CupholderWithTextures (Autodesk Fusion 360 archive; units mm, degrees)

design "Final Project" references "Servo_motor", "EIP Cupholder PCB", "Arcade Button_30mm"
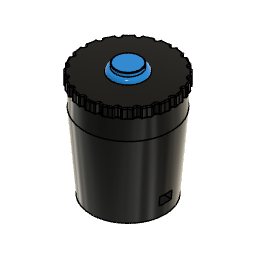
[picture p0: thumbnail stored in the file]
parameter "CupHolderBottomDiameter" = 76.2
parameter "CupHolderTopDiameter" = 88.9
parameter "CupHolderHeight" = 76.2
parameter "CupHolderThickness" = 10 comment "Only for visual CAD  purposes"
parameter "CupHolderTolerance" = 2 comment "Between cup holder and the mechanism case"
parameter "LidHeight" = 30
parameter "CupHolderCaseThickness" = 10
parameter "LockingMechanismProtrusionWidth" = 5
parameter "LockingMechanismTolerance" = 1
parameter "LockingMechanismProtrusionHeight" = 5
parameter "LockingMechanismProtrusionDistance" = 5
parameter "LockingMechanismAngle" = 20
parameter "ArcadeButtonDiameter" = 30
parameter "MirrorAttachmentCurlThickness" = 2
sketch "Sketch2" plane through (0, 0, 0) normal (0, 0, 1) x axis (1, 0, 0)
  circle C1 centre (0, 0) radius 38.1
  point P1 (0, 0)
  point P2 (0, 0)
  coincident P1 P2
  dimension "d3" diameter C1 = 76.2 (= "CupHolderBottomDiameter")
work_plane "WorkPlane1" sketch "Sketch2" AlongDistance 76.2 (= "CupHolderHeight")
sketch "Sketch3" plane through (0, 0, 76.2) normal (0, 0, 1) x axis (1, 0, 0)
  circle C1 centre (0, 0) radius 44.45
  point P1 (0, 0)
  point P2 (0, 0)
  coincident P1 P2
  dimension "d6" diameter C1 = 88.9 (= "CupHolderTopDiameter")
loft "Loft1" sketch "Sketch2" + "Sketch3"
sketch "Sketch4" plane through (0, 0, 0) normal (0, 0, 1) x axis (1, 0, 0)
  circle C1 centre (0, 0) radius 88.9
  point P1 (0, 0)
  point P2 (0, 0)
  coincident P1 P2
  dimension "d7" diameter C1 = 177.8 (= "CupHolderTopDiameter * 2")
extrude "Extrude1" new body sketch "Sketch4" along normal blind 76.2 (= "CupHolderHeight")
extrude "Extrude2" new body of existing geometry blind 10 (= "CupHolderThickness") bodies "CupHolder"
combine "Combine2"
combine "Combine1"
sketch "Sketch1" plane through (0, 0, 0) normal (0, 0, 1) x axis (1, 0, 0)
  circle C1 centre (0, 0) radius 44.45
  point P1 (0, 0)
  point P2 (0, 0)
  coincident P1 P2
  dimension "d15" diameter C1 = 88.9 (= "CupHolderTopDiameter")
extrude "Extrude1" new body sketch "Sketch1" along normal blind 76.2 (= "CupHolderHeight")
combine "Combine1"
copy_paste "CutPaste1"
offset_faces "OffsetFaces1"
extrude "Extrude2" add of existing geometry blind 30 (= "LidHeight")
shell "Shell2" innerThickness 10 (= "CupHolderThickness")
split "Split4" bodies "CupHolderCase"
sketch "Sketch4" plane through (0, 0, 96.2) normal (0, 0, -1) x axis (1, 0, 0)
  circle C1 centre (0, 0) radius 42.4431
  circle C2 centre (0, 0) radius 32.4431
extrude "Extrude4" new body sketch "Sketch4" profile of C2 along normal blind 20 (= "LidHeight - CupHolderThickness")
combine "Combine4"
sketch "Sketch5" plane through (0, 0, 76.2) normal (0, 0, -1) x axis (1, 0, 0)
  line L1 (0, -32.4431) -> (0, -36.9654)
  line L2 (3, -32.4431) -> (0, -32.4431)
  line L3 (3, -25.4431) -> (3, -32.4431)
  line L4 (0, -25.4431) -> (3, -25.4431)
  line L5 (-3, -32.4431) -> (0, -32.4431)
  line L6 (-3, -25.4431) -> (-3, -32.4431)
  line L7 (0, -25.4431) -> (-3, -25.4431)
  circle C1 centre (0, 0) radius 32.4431
  point P4 (0, -32.4431)
  point P8 (0, -32.4431)
  point P5 (3, -32.4431)
  point P9 (-3, -32.4431)
  point P6 (3, -25.4431)
  point P10 (-3, -25.4431)
  point P7 (0, -25.4431)
  point P11 (0, -25.4431)
  coincident C1 P4
  vertical L1
  tangent C1 L2
  perpendicular L1 L2
  perpendicular L2 L3
  perpendicular L3 L4
  symmetric P4 L1 P8
  symmetric L1 P5 P9
  symmetric L1 P6 P10
  symmetric L1 P7 P11
  dimension "d37" distance P4 P5 = 3 (= "LockingMechanismProtrusionWidth / 2 + LockingMechanismTolerance / 2")
  dimension "d39" distance P5 P6 = 7 (= "LockingMechanismProtrusionDistance + CupHolderTolerance")
extrude "Extrude5" cut sketch "Sketch5" profile of C1 L3 L4 L6 L7 against normal blind 20
sketch "Sketch6" plane through (0, 0, 96.2) normal (0, 0, -1) x axis (1, 0, 0)
  line L1 (3, -25.4431) -> (3, -32.3041)
  line L2 (-3, -25.4431) -> (3, -25.4431)
  line L3 (-3, -32.3041) -> (-3, -25.4431)
  line L4 (-8.702, -23.9087) -> (0, 0)
  line L5 (0, -25.4431) -> (0, 0)
  line L6 (-11.0962, -30.4865) -> (-8.702, -23.9087)
  line L7 (-3, -25.2656) -> (-3, -25.4431)
  arc A1 centre (0, 0) radius 32.4431 clockwise from (-3, -32.3041) to (3, -32.3041)
  circle C1 centre (0, 0) radius 42.4431
  arc A2 centre (0, 0) radius 25.4431 clockwise from (0, -25.4431) to (-8.702, -23.9087)
  point P9 (0, -25.4431)
  point P1 (0, 0)
  point P7 (0, 0)
  point P10 (-11.0962, -30.4865)
  point P6 (-3, -25.4431)
  point P11 (-3, -25.4431)
  point P12 (-3, -25.2656)
  midpoint L2 P9
  coincident P1 P7
  coincident A1 P10
  parallel L4 L6
  coincident P6 P11
  coincident A2 P12
  perpendicular L2 L7
  dimension "d43" angle L4 L5 = 20 (= "LockingMechanismAngle")
extrude "Extrude6" cut sketch "Sketch6" profile of A1 L3 A2 L6 L7 along normal blind 6 (= "LockingMechanismProtrusionHeight + LockingMechanismTolerance")
extrude "Extrude7" cut sketch "Sketch6" profile of L2 A2 L7 along normal blind 20
sketch "Sketch7" plane through (0, 0, 0) normal (0.9397, 0.342, 0) x axis (-0.342, 0.9397, 0)
  line L1 (25.4431, 96.2) -> (32.4431, 96.2)
  line L2 (25.4431, 90.2) -> (25.4431, 96.2)
  line L3 (32.4431, 90.2) -> (25.4431, 90.2)
  line L4 (32.4431, 96.2) -> (32.4431, 90.2)
  line L5 (32.4431, 91.2) -> (32.4431, 90.2)
  line L6 (25.4431, 91.2) -> (32.4431, 91.2)
  point P5 (32.4431, 90.2)
  point P6 (32.4431, 90.2)
  point P7 (32.4431, 91.2)
  point P8 (25.4431, 91.2)
  coincident P5 P6
  coincident L4 P7
  coincident L2 P8
  perpendicular L2 L6
  dimension "d48" distance P6 P7 = 1 (= "LockingMechanismTolerance")
loft "Loft3" sketch "Sketch7"
circular_pattern "C-Pattern1" TotalAngle 360
fillet "Fillet2" radius 1 1
sketch "Sketch8" plane through (0, 0, 96.2) normal (0, 0, 1) x axis (-1, 0, 0)
  line L1 (2.2086, -32.4642) -> (-0.2913, -32.4418)
  line L2 (2.2535, -27.4644) -> (2.2086, -32.4642)
  line L3 (-0.4431, -27.4402) -> (2.2535, -27.4644)
  line L4 (-0.4431, -27.4402) -> (-0.2913, -32.4418)
  line L5 (-2.7852, -32.6157) -> (-0.2913, -32.4418)
  line L6 (-3.1332, -27.6279) -> (-2.7852, -32.6157)
  line L7 (-0.4431, -27.4402) -> (-3.1332, -27.6279)
  circle C1 centre (0, 0) radius 32.4431
  circle C2 centre (0, 0) radius 42.4431
  point P3 (-0.2913, -32.4418)
  point P7 (-0.2913, -32.4418)
  point P4 (2.2086, -32.4642)
  point P8 (-2.7852, -32.6157)
  point P5 (2.2535, -27.4644)
  point P9 (-3.1332, -27.6279)
  point P6 (-0.4431, -27.4402)
  point P10 (-0.4431, -27.4402)
  coincident C1 P3
  tangent C1 L1
  perpendicular L1 L2
  perpendicular L2 L3
  symmetric P3 L4 P7
  symmetric P4 L4 P8
  symmetric P5 L4 P9
  symmetric P6 L4 P10
  dimension "d51" distance P3 P4 = 2.5 (= "LockingMechanismProtrusionWidth / 2")
  dimension "d52" distance P4 P5 = 5
extrude "Extrude8" add sketch "Sketch8" profile of C1 L2 L3 L6 L7 no distance stored
fillet "Fillet1" radius 1
circular_pattern "C-Pattern2" TotalAngle 360
sketch "Sketch9" plane through (0, 0, 106.2) normal (0, 0, 1) x axis (-1, 0, 0)
  line L1 (-13.5367, -40.2265) -> (0, 0)
  line L2 (-0.4435, -42.4408) -> (0, 0)
  line L3 (0, 0) -> (-7.0772, -41.8489)
  line L4 (-19.6113, -115.9654) -> (-7.0772, -41.8489)
  curve K1 (-7.4119, -43.8277) -> (-0.4435, -42.4408)
  curve K2 (-0.847, -42.4391) -> (-0.04, -42.4424)
  line L5 (-10.6726, -43.2763) -> (-7.4119, -43.8277)
  curve K3 (-9.0422, -43.552) -> (-5.7815, -44.1034)
  curve K4 (-7.4119, -43.8277) -> (-13.5367, -40.2265)
  curve K5 (-13.1551, -40.3576) -> (-13.9183, -40.0954)
  curve K6 (-5.7815, -44.1034) -> (-9.0422, -43.552)
  circle C1 centre (0, 0) radius 42.4431
  arc A1 centre (0, 0) radius 42.4431 clockwise from (-0.4435, -42.4408) to (-13.5367, -40.2265)
  point P5 (-0.4435, -42.4408)
  point P1 (0, 0)
  point P3 (0, 0)
  point P6 (-7.0772, -41.8489)
  point P7 (-7.0772, -41.8489)
  point P8 (0, 0)
  point P9 (-7.0772, -41.8489)
  point P12 (-7.4119, -43.8277)
  point P17 (-9.0422, -43.552)
  point P18 (-13.5367, -40.2265)
  point P11 (-4.9088, -86.9573)
  point P19 (-23.9577, -83.7359)
  point P20 (-7.4119, -43.8277)
  point P13 (-0.04, -42.4424)
  point P21 (-13.9183, -40.0954)
  point P14 (-0.847, -42.4391)
  point P22 (-13.1551, -40.3576)
  point P16 (-5.7815, -44.1034)
  point P23 (-9.0422, -43.552)
  point P24 (-5.7815, -44.1034)
  coincident C1 P5
  coincident P1 P3
  midpoint A1 P6
  coincident P6 P7
  coincident P1 P8
  coincident P6 P9
  parallel L3 L4
  coincident L4 P12
  midpoint P5 K2
  perpendicular L4 L5
  midpoint P12 K3
  midpoint L5 P17
  parallel L5 K3
  symmetric P5 L4 P18
  symmetric L4 P11 P19
  symmetric L4 P12 P20
  symmetric L4 P13 P21
  symmetric L4 P14 P22
  symmetric L4 P16 P23
  symmetric L4 P17 P24
  dimension "d64" angle L1 L2 = 18 (= "( 360 / NumGripsTopLid ) * 1 deg")
  dimension "d153" distance P8 P12 = 44.45 (= "CupHolderTopDiameter / 2")
extrude "Extrude9" new body sketch "Sketch9" profile of C1 K1 K4 against normal blind 10
combine "Combine6"
circular_pattern "C-Pattern4" TotalAngle 360
component_from_bodies "Body->Comp1"
component_from_bodies "Body->Comp2"
fillet "Fillet1" radius 1
fillet "Fillet2" radius 1
sketch "Sketch10" plane through (0, 0, 76.2) normal (0, 0, -1) x axis (1, 0, 0)
  line L1 (24.1136, -4) -> (31.1876, -4)
  line L2 (24.4431, 4) -> (24.4431, 0)
  line L3 (31.1876, 4) -> (24.4431, 4)
  line L4 (4, 24.1136) -> (4, 31.1876)
  line L5 (-4, 24.4431) -> (0, 24.4431)
  line L6 (-4, 31.1876) -> (-4, 24.4431)
  line L7 (-24.1136, 4) -> (-31.1876, 4)
  line L8 (-24.4431, -4) -> (-24.4431, 0)
  line L9 (-31.1876, -4) -> (-24.4431, -4)
  line L10 (-4, -24.1136) -> (-4, -31.1876)
  line L11 (4, -24.4431) -> (0, -24.4431)
  line L12 (4, -31.1876) -> (4, -24.4431)
  arc A1 centre (0, 0) radius 24.4431 clockwise from (24.4431, 0) to (24.1136, -4)
  arc A2 centre (0, 0) radius 31.4431 clockwise from (4, 31.1876) to (31.1876, 4)
  arc A3 centre (0, 0) radius 24.4431 clockwise from (0, 24.4431) to (4, 24.1136)
  arc A4 centre (0, 0) radius 31.4431 clockwise from (-31.1876, 4) to (-4, 31.1876)
  arc A5 centre (0, 0) radius 24.4431 clockwise from (-24.4431, 0) to (-24.1136, 4)
  arc A6 centre (0, 0) radius 31.4431 clockwise from (-4, -31.1876) to (-31.1876, -4)
  arc A7 centre (0, 0) radius 24.4431 clockwise from (0, -24.4431) to (-4, -24.1136)
  arc A8 centre (0, 0) radius 31.4431 clockwise from (31.1876, -4) to (4, -31.1876)
  circle C1 centre (0, 0) radius 22.5
  concentric A1 C1
  dimension "d155" diameter C1 = 45 (= "ArcadeButtonDiameter + 15 mm")
extrude "Extrude1" cut sketch "Sketch10" profile of C1 against normal blind 20
fillet "Fillet3" radius 1
fillet "Fillet4" radius 1
sketch "Sketch11" plane through (0, 0, 96.2) normal (0, 0, -1) x axis (1, 0, 0)
  circle C1 centre (0, 0) radius 21.5
  circle C2 centre (0, 0) radius 15
  point P1 (0, 0)
  point P3 (0, 0)
  coincident P1 P3
  dimension "d82" diameter C2 = 30 (= "ArcadeButtonDiameter")
extrude "Extrude2" cut sketch "Sketch11" profile of C2 against normal blind 10
component_insert "Component Insert1"
joint "Assemble1" alignAngle 0 alignOffsetX 0 alignOffsetY 0 alignOffsetZ 0
as_built_joint "As-built1" OffsetX 0 OffsetY 0 OffsetZ 0 AngleZ 0 AngleMaximum 0
joint "Assemble1" alignAngle 0 alignOffsetX 0 alignOffsetY 0 alignOffsetZ -130 DistanceMaximum 0 DistanceRest 0
base_feature "Base Feature1"
base_feature "Base Feature1"
base_feature "Base Feature1"
base_feature "Base Feature1"
base_feature "Base Feature1"
base_feature "Base Feature1"
base_feature "Base Feature1"
base_feature "Base Feature1"
base_feature "Base Feature1"
base_feature "Base Feature1"
base_feature "Base Feature1"
sketch "Sketch4" plane through (-0.0164, 0, -21.4157) normal (-0.0008, 0, -1) x axis (0, -1, 0)
  line L1 (-46.2621, -82.9366) -> (-46.2621, -20.9366)
  line L2 (51.0689, -82.9366) -> (-46.2621, -82.9366)
  line L3 (51.0689, -20.9366) -> (51.0689, -82.9366)
  line L4 (-46.2621, -20.9366) -> (51.0689, -20.9366)
  line L5 (8.573, -42.2771) -> (8.573, -31.2771)
  line L6 (-4.427, -44.2771) -> (6.573, -44.2771)
  line L7 (-6.427, -31.2771) -> (-6.427, -42.2771)
  line L8 (6.573, -29.2771) -> (-4.427, -29.2771)
  line L9 (-123.9966, -211.3616) -> (128.8034, -211.3616)
  line L10 (-123.9966, -20.9366) -> (-123.9966, -211.3616)
  line L11 (128.8034, -20.9366) -> (-123.9966, -20.9366)
  line L12 (128.8034, -211.3616) -> (128.8034, -20.9366)
  arc A1 centre (6.573, -42.2771) radius 2 clockwise from (8.573, -42.2771) to (6.573, -44.2771)
  arc A2 centre (-4.427, -42.2771) radius 2 clockwise from (-4.427, -44.2771) to (-6.427, -42.2771)
  arc A3 centre (-4.427, -31.2771) radius 2 clockwise from (-6.427, -31.2771) to (-4.427, -29.2771)
  arc A4 centre (6.573, -31.2771) radius 2 clockwise from (6.573, -29.2771) to (8.573, -31.2771)
  point P22 (2.4034, -20.9366)
  point P23 (2.4034, -20.9366)
  point P18 (128.8034, -211.3616)
  point P19 (-123.9966, -211.3616)
  point P20 (-123.9966, -20.9366)
  horizontal L9
  vertical L10
  horizontal L11
  vertical L12
  midpoint L11 P22
  midpoint L4 P23
  coincident P22 P23
  dimension "d128" distance P18 P19 = 252.8
  dimension "d129" distance P19 P20 = 190.425
extrude "Extrude2" new body sketch "Sketch4" profile of L1 L2 L3 L9 L10 L11 L12 against normal blind 2
combine "Combine3"
copy_paste_bodies "CutPasteBodies1"
remove_body "RemoveBody1"
sketch "Sketch5" plane through (-0.0164, 0, -21.4157) normal (-0.0008, 0, -1) x axis (0, -1, 0)
  line L1 (8.573, -42.2771) -> (8.573, -31.2771)
  line L2 (-4.427, -44.2771) -> (6.573, -44.2771)
  line L3 (-6.427, -31.2771) -> (-6.427, -42.2771)
  line L4 (6.573, -29.2771) -> (-4.427, -29.2771)
  line L5 (-123.9966, -20.9366) -> (128.8034, -20.9366)
  line L6 (-123.9966, -211.3616) -> (-123.9966, -20.9366)
  line L7 (128.8034, -211.3616) -> (-123.9966, -211.3616)
  line L8 (128.8034, -20.9366) -> (128.8034, -211.3616)
  line L9 (121.8034, -211.3616) -> (128.8034, -211.3616)
  line L10 (121.8034, -204.3616) -> (121.8034, -211.3616)
  line L11 (128.8034, -204.3616) -> (121.8034, -204.3616)
  line L12 (128.8034, -211.3616) -> (128.8034, -204.3616)
  arc A1 centre (6.573, -42.2771) radius 2 clockwise from (8.573, -42.2771) to (6.573, -44.2771)
  arc A2 centre (-4.427, -42.2771) radius 2 clockwise from (-4.427, -44.2771) to (-6.427, -42.2771)
  arc A3 centre (-4.427, -31.2771) radius 2 clockwise from (-6.427, -31.2771) to (-4.427, -29.2771)
  arc A4 centre (6.573, -31.2771) radius 2 clockwise from (6.573, -29.2771) to (8.573, -31.2771)
  circle C1 centre (121.8034, -204.3616) radius 2
  point P17 (128.8034, -211.3616)
  point P18 (128.8034, -211.3616)
  point P20 (121.8034, -204.3616)
  point P22 (121.8034, -204.3616)
  point P21 (128.8034, -204.3616)
  point P19 (121.8034, -211.3616)
  horizontal L9
  vertical L10
  horizontal L11
  vertical L12
  coincident P17 P18
  coincident P20 P22
  dimension "d132" distance P18 P21 = 7
  dimension "d133" distance P18 P19 = 7
  dimension "d134" diameter C1 = 4
extrude "Extrude1" cut sketch "Sketch5" profile of C1 against normal blind 2
work_plane "WorkPlane3"
work_plane "WorkPlane4"
mirror "Mirror1" mirrorStitchTolerance 0.1
mirror "Mirror2" mirrorStitchTolerance 0.1
extrude "Extrude2" cut of existing geometry blind -0.85 (= "-( 2 mm - 1.15 mm )")
sketch "Sketch6" plane through (-0.0157, 0, -20.5657) normal (-0.0008, 0, -1) x axis (0, -1, 0)
  line L1 (8.573, -42.2771) -> (8.573, -31.2771)
  line L2 (-4.427, -44.2771) -> (6.573, -44.2771)
  line L3 (-6.427, -31.2771) -> (-6.427, -42.2771)
  line L4 (6.573, -29.2771) -> (-4.427, -29.2771)
  line L5 (-123.9966, -20.9366) -> (128.8034, -20.9366)
  line L6 (-123.9966, -211.3616) -> (-123.9966, -20.9366)
  line L7 (128.8034, -211.3616) -> (-123.9966, -211.3616)
  line L8 (128.8034, -20.9366) -> (128.8034, -211.3616)
  line L9 (-123.9966, -211.3616) -> (128.8034, -211.3616)
  line L10 (-123.9966, -20.9366) -> (-123.9966, -211.3616)
  line L11 (128.8034, -20.9366) -> (-123.9966, -20.9366)
  line L12 (128.8034, -211.3616) -> (128.8034, -20.9366)
  line L13 (-98.9966, -185.8616) -> (103.8034, -185.8616)
  line L14 (-98.9966, -46.4366) -> (-98.9966, -185.8616)
  line L15 (103.8034, -46.4366) -> (-98.9966, -46.4366)
  line L16 (103.8034, -185.8616) -> (103.8034, -46.4366)
  line L17 (-98.9966, -46.4366) -> (103.8034, -185.8616)
  line L18 (103.8034, -46.4366) -> (-98.9966, -185.8616)
  line L19 (-123.9966, -20.9366) -> (128.8034, -211.3616)
  line L20 (128.8034, -20.9366) -> (-123.9966, -211.3616)
  circle C1 centre (-116.9966, -27.9366) radius 2
  circle C2 centre (-116.9966, -204.3616) radius 2
  circle C3 centre (121.8034, -27.9366) radius 2
  circle C4 centre (121.8034, -204.3616) radius 2
  arc A1 centre (6.573, -42.2771) radius 2 clockwise from (8.573, -42.2771) to (6.573, -44.2771)
  arc A2 centre (-4.427, -42.2771) radius 2 clockwise from (-4.427, -44.2771) to (-6.427, -42.2771)
  arc A3 centre (-4.427, -31.2771) radius 2 clockwise from (-6.427, -31.2771) to (-4.427, -29.2771)
  arc A4 centre (6.573, -31.2771) radius 2 clockwise from (6.573, -29.2771) to (8.573, -31.2771)
  point P19 (-123.9966, -20.9366)
  point P24 (-123.9966, -20.9366)
  point P21 (128.8034, -211.3616)
  point P22 (128.8034, -211.3616)
  point P30 (2.4034, -116.1491)
  point P31 (2.4034, -116.1491)
  point P26 (103.8034, -185.8616)
  point P27 (-98.9966, -185.8616)
  point P29 (103.8034, -46.4366)
  horizontal L9
  vertical L10
  horizontal L11
  vertical L12
  coincident P19 P24
  coincident P21 P22
  horizontal L13
  vertical L14
  horizontal L15
  vertical L16
  midpoint L18 P30
  midpoint L20 P31
  coincident P30 P31
  dimension "d143" distance P26 P27 = 202.8
  dimension "d144" distance P26 P29 = 139.425
extrude "Extrude3" new body sketch "Sketch6" profile of C1 C2 C3 C4 L1 A1 L2 A2 L3 A3 L4 A4 L5 L6 L7 L8 L9 L10 L11 L12 L13 L14 L15 L16 along normal blind 1.125
extrude "Extrude4" new body sketch "Sketch6" profile of L13 L14 L15 L16 along normal blind 1.125
move "Move1"
sketch "Sketch7" plane through (-0.0157, 0, -20.5657) normal (-0.0008, 0, -1) x axis (0, -1, 0)
  line L1 (8.573, -42.2771) -> (8.573, -31.2771)
  line L2 (-4.427, -44.2771) -> (6.573, -44.2771)
  line L3 (-6.427, -31.2771) -> (-6.427, -42.2771)
  line L4 (6.573, -29.2771) -> (-4.427, -29.2771)
  line L5 (-123.9966, -20.9366) -> (128.8034, -20.9366)
  line L6 (-123.9966, -211.3616) -> (-123.9966, -20.9366)
  line L7 (128.8034, -211.3616) -> (-123.9966, -211.3616)
  line L8 (128.8034, -20.9366) -> (128.8034, -211.3616)
  line L9 (-123.9966, -211.3616) -> (128.8034, -211.3616)
  line L10 (-123.9966, -20.9366) -> (-123.9966, -211.3616)
  line L11 (128.8034, -20.9366) -> (-123.9966, -20.9366)
  line L12 (128.8034, -211.3616) -> (128.8034, -20.9366)
  line L13 (-107.0466, -194.4116) -> (111.8534, -194.4116)
  line L14 (-107.0466, -37.8866) -> (-107.0466, -194.4116)
  line L15 (111.8534, -37.8866) -> (-107.0466, -37.8866)
  line L16 (111.8534, -194.4116) -> (111.8534, -37.8866)
  line L17 (-107.0466, -37.8866) -> (111.8534, -194.4116)
  line L18 (111.8534, -37.8866) -> (-107.0466, -194.4116)
  line L19 (-123.9966, -20.9366) -> (128.8034, -211.3616)
  line L20 (128.8034, -20.9366) -> (-123.9966, -211.3616)
  circle C1 centre (-116.9966, -27.9366) radius 2
  circle C2 centre (-116.9966, -204.3616) radius 2
  circle C3 centre (121.8034, -27.9366) radius 2
  circle C4 centre (121.8034, -204.3616) radius 2
  arc A1 centre (6.573, -42.2771) radius 2 clockwise from (8.573, -42.2771) to (6.573, -44.2771)
  arc A2 centre (-4.427, -42.2771) radius 2 clockwise from (-4.427, -44.2771) to (-6.427, -42.2771)
  arc A3 centre (-4.427, -31.2771) radius 2 clockwise from (-6.427, -31.2771) to (-4.427, -29.2771)
  arc A4 centre (6.573, -31.2771) radius 2 clockwise from (6.573, -29.2771) to (8.573, -31.2771)
  point P19 (-123.9966, -20.9366)
  point P24 (-123.9966, -20.9366)
  point P21 (128.8034, -211.3616)
  point P22 (128.8034, -211.3616)
  point P30 (2.4034, -116.1491)
  point P31 (2.4034, -116.1491)
  point P26 (111.8534, -194.4116)
  point P27 (-107.0466, -194.4116)
  point P29 (111.8534, -37.8866)
  horizontal L9
  vertical L10
  horizontal L11
  vertical L12
  coincident P19 P24
  coincident P21 P22
  horizontal L13
  vertical L14
  horizontal L15
  vertical L16
  midpoint L18 P30
  midpoint L20 P31
  coincident P30 P31
  dimension "d149" distance P26 P27 = 218.9
  dimension "d150" distance P26 P29 = 156.525
extrude "Extrude3" new body sketch "Sketch7" profile of C1 C2 C3 C4 L1 L3 A3 L4 A4 L5 L6 L7 L8 L9 L10 L11 L12 L13 L14 L15 L16 along normal blind 1.15
copy_paste_bodies "CutPasteBodies2"
sketch "pcb-sketch" plane through (0, 0, 183.1) normal (0, 0, -1) x axis (1, 0, 0)
  circle C1 centre (0, 0) radius 15
  circle C2 centre (0, 0) radius 21.5
  circle C3 centre (0, 0) radius 20.5
  dimension "d156" = -1
component_insert "Component Insert5"
step "Context"
sketch "Sketch9" plane through (0, 0, 183.1) normal (0, 0, -1) x axis (1, 0, 0)
  line L1 (-8, 0) -> (0, 0)
  point P1 (0, 0)
  point P2 (0, 0)
  coincident P1 P2
  horizontal L1
work_plane "WorkPlane5"
sketch "Sketch10" plane through (25.4431, 0, 164.1) normal (0, 1, 0) x axis (1, 0, 0)
  line L1 (-25.4431, -24) -> (-25.4431, -19)
  point P2 (-25.4431, -19)
  point P3 (-25.4431, -19)
  coincident P2 P3
  vertical L1
remove_instance "RemoveInstance1"
remove_instance "RemoveInstance2"
remove_instance "RemoveInstance3"
remove_instance "RemoveInstance4"
remove_instance "RemoveInstance5"
remove_instance "RemoveInstance6"
remove_instance "RemoveInstance7"
remove_instance "RemoveInstance8"
remove_instance "RemoveInstance9"
remove_instance "RemoveInstance10"
remove_instance "RemoveInstance11"
remove_instance "RemoveInstance12"
remove_instance "RemoveInstance13"
component_insert "Component Insert6"
copy_paste "CutPaste1"
position "Position2"
sketch "Sketch11" plane through (0, 0, 0) normal (1, 0, 0) x axis (0, 1, 0)
  line L1 (-6, 107.3995) -> (6, 107.3995)
  line L2 (-6, 99.3995) -> (-6, 107.3995)
  line L3 (6, 99.3995) -> (-6, 99.3995)
  line L4 (6, 107.3995) -> (6, 99.3995)
  line L5 (-6, 99.3995) -> (6, 107.3995)
  line L6 (6, 99.3995) -> (-6, 107.3995)
  point P6 (0, 103.3995)
  point P4 (-6, 99.3995)
  point P5 (6, 99.3995)
  point P3 (-6, 107.3995)
  horizontal L1
  perpendicular L1 L2
  parallel L1 L3
  parallel L2 L4
  coincident L5 P6
  coincident L6 P6
  dimension "d157" distance P4 P5 = 12
  dimension "d158" distance P3 P4 = 8
extrude "Extrude1" cut sketch "Sketch11" profile of L1 L2 L3 L4 along normal blind 100
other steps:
base_feature "Base Feature1" bodies "CupHolderCase"
base_feature "Base Feature2"
base_feature "Base Feature3"
base_feature "Base Feature1" bodies "Lid"
create_component "CreateComponent1"
create_component "CreateComponent1"
remove_instance "RemoveInstance1"
create_component "CreateComponent1"
remove_body "RemoveBody2"
create_component "CreateComponent2"
remove_body "RemoveBody3"
joint_origin "JointOrigin1"
joint_origin "JointOrigin3"
joint_origin "JointOrigin3"
create_component "CreateComponent1"
create_component "CreateComponent2"
create_component "CreateComponent3"
create_component "CreateComponent4"
create_component "CreateComponent5"
create_component "CreateComponent6"
create_component "CreateComponent7"
create_component "CreateComponent8"
create_component "CreateComponent9"
create_component "CreateComponent10"
create_component "CreateComponent11"
create_component "CreateComponent3"
remove_body "RemoveBody2"
remove_body "RemoveBody3"
remove_body "RemoveBody4"
remove_instance "RemoveInstance1"
named bodies: "CupHolder", "Lid", "CupHolderCase"

design "Servo_motor"
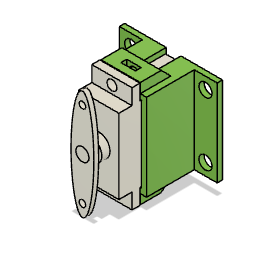
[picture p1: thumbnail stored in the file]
parameter "servo_height" = 22.8
parameter "servo_width" = 12.25
parameter "servo_length" = 22.8
parameter "servo_ears_width" = 4.745 (= "( ( 32.29 - 22.8 ) / 2 ) * 1 mm")
parameter "servo_ears_holes" = 3
parameter "servo_ears_thickness" = 2.44
parameter "servo_axle_diameter" = 6.85
parameter "servo_axle_length" = 5
parameter "servo_enclosure_margin" = 0.2
parameter "servo_enclosure_wall_thickness" = 1.6
parameter "servo_enclosure_ears_width" = 7
parameter "servo_enclosure_ears_screws" = 4
parameter "servo_ears_shift" = 4
parameter "servo_enclosure_cable_hole_height" = 6.5
parameter "servo_enclosure_cable_hole_width" = 4.5
parameter "d1322" = 0
parameter "d1323" = 0
parameter "d1324" = 0
parameter "d1325" = 0
parameter "d1609" = 0
parameter "d1610" = 0
parameter "d1611" = 0
parameter "d1612" = 0
parameter "d1621" = 0
parameter "d1622" = 0
parameter "d1623" = 0
parameter "d1624" = 0
parameter "d1698" = 0
parameter "d1699" = 0
parameter "d1700" = 0
parameter "d1701" = 0
parameter "d1706" = 0
parameter "d1707" = 0
parameter "d1708" = 0
parameter "d1709" = 0
parameter "d1714" = 0
parameter "d1715" = 0
parameter "d1716" = 0
parameter "d1717" = 0
parameter "d1726" = 0
parameter "d1727" = 0
parameter "d1728" = 0
parameter "d1729" = 0
base_feature "Base Feature1"
sketch "Sketch1" plane through (0, 0, 6) normal (0, 0, 1) x axis (1, 0, 0)
  line L1 (62.5, -47) -> (22.5, -47)
  line L2 (62.5, -53) -> (62.5, -47)
  line L3 (22.5, -53) -> (62.5, -53)
  line L4 (22.5, -47) -> (22.5, -53)
  line L5 (62.5, 103) -> (22.5, 103)
  line L6 (62.5, 97) -> (62.5, 103)
  line L7 (22.5, 97) -> (62.5, 97)
  line L8 (22.5, 103) -> (22.5, 97)
  line L9 (-98.7963, 175) -> (-27.5, 120)
  line L10 (-150, 175) -> (-98.7963, 175)
  line L11 (-150, -175) -> (-150, 175)
  line L12 (150, -175) -> (-150, -175)
  line L13 (150, 175) -> (150, -175)
  line L14 (98.7963, 175) -> (150, 175)
  line L15 (27.5, 120) -> (98.7963, 175)
  line L16 (-27.5, 120) -> (27.5, 120)
  line L17 (22.5, -3) -> (62.5, -3)
  line L18 (22.5, 3) -> (22.5, -3)
  line L19 (62.5, 3) -> (22.5, 3)
  line L20 (62.5, -3) -> (62.5, 3)
  line L21 (-22.5, -97) -> (-62.5, -97)
  line L22 (-22.5, -103) -> (-22.5, -97)
  line L23 (-62.5, -103) -> (-22.5, -103)
  line L24 (-62.5, -97) -> (-62.5, -103)
  line L25 (-22.5, 103) -> (-62.5, 103)
  line L26 (-22.5, 97) -> (-22.5, 103)
  line L27 (-62.5, 97) -> (-22.5, 97)
  line L28 (-62.5, 103) -> (-62.5, 97)
  line L29 (-22.5, 53) -> (-62.5, 53)
  line L30 (-22.5, 47) -> (-22.5, 53)
  line L31 (-62.5, 47) -> (-22.5, 47)
  line L32 (-62.5, 53) -> (-62.5, 47)
  line L33 (62.5, 53) -> (22.5, 53)
  line L34 (62.5, 47) -> (62.5, 53)
  line L35 (22.5, 47) -> (62.5, 47)
  line L36 (22.5, 53) -> (22.5, 47)
  line L37 (-22.5, -147) -> (-62.5, -147)
  line L38 (-22.5, -153) -> (-22.5, -147)
  line L39 (-62.5, -153) -> (-22.5, -153)
  line L40 (-62.5, -147) -> (-62.5, -153)
  line L41 (-22.5, -47) -> (-62.5, -47)
  line L42 (-22.5, -53) -> (-22.5, -47)
  line L43 (-62.5, -53) -> (-22.5, -53)
  line L44 (-62.5, -47) -> (-62.5, -53)
  line L45 (-22.5, 3) -> (-62.5, 3)
  line L46 (-22.5, -3) -> (-22.5, 3)
  line L47 (-62.5, -3) -> (-22.5, -3)
  line L48 (-62.5, 3) -> (-62.5, -3)
  line L49 (62.5, -97) -> (22.5, -97)
  line L50 (62.5, -103) -> (62.5, -97)
  line L51 (22.5, -103) -> (62.5, -103)
  line L52 (22.5, -97) -> (22.5, -103)
  line L53 (62.5, -147) -> (22.5, -147)
  line L54 (62.5, -153) -> (62.5, -147)
  line L55 (22.5, -153) -> (62.5, -153)
  line L56 (22.5, -147) -> (22.5, -153)
  line L57 (80, 2) -> (80, -118)
  line L58 (120, 12) -> (90, 12)
  line L59 (130, -118) -> (130, 2)
  line L60 (90, -128) -> (120, -128)
  line L61 (-80, -118) -> (-80, 2)
  line L62 (-120, -128) -> (-90, -128)
  line L63 (-130, 2) -> (-130, -118)
  line L64 (-90, 12) -> (-120, 12)
  line L65 (-6.125, 120) -> (6.125, 120)
  line L66 (-6.125, 97.2) -> (-6.125, 120)
  line L67 (6.125, 97.2) -> (-6.125, 97.2)
  line L68 (6.125, 120) -> (6.125, 97.2)
  arc A1 centre (90, 2) radius 10 clockwise from (80, 2) to (90, 12)
  arc A2 centre (120, 2) radius 10 clockwise from (120, 12) to (130, 2)
  arc A3 centre (120, -118) radius 10 clockwise from (130, -118) to (120, -128)
  arc A4 centre (90, -118) radius 10 clockwise from (90, -128) to (80, -118)
  circle C1 centre (-132.5, 155) radius 3
  circle C2 centre (132.5, 155) radius 3
  circle C3 centre (132.5, -155) radius 3
  arc A5 centre (-90, -118) radius 10 clockwise from (-80, -118) to (-90, -128)
  arc A6 centre (-120, -118) radius 10 clockwise from (-120, -128) to (-130, -118)
  arc A7 centre (-120, 2) radius 10 clockwise from (-130, 2) to (-120, 12)
  arc A8 centre (-90, 2) radius 10 clockwise from (-90, 12) to (-80, 2)
  circle C4 centre (-132.5, -155) radius 3
  point P86 (6.125, 120)
  point P87 (-6.125, 120)
  point P89 (6.125, 97.2)
  horizontal L65
  vertical L66
  horizontal L67
  vertical L68
  coincident L16 P86
  midpoint L16 L65
  dimension "d928" distance P86 P87 = 12.25 (= "servo_width")
  dimension "d929" distance P86 P89 = 22.8 (= "servo_length")
extrude "Extrude1" new body sketch "Sketch1" profile of L16 L65 L66 L67 L68 along normal blind 22.8 (= "servo_height")
sketch "Sketch2" plane through (0, 0, 28.8) normal (0, 0, 1) x axis (1, 0, 0)
  line L1 (6.125, 120) -> (6.125, 97.2)
  line L2 (-6.125, 120) -> (6.125, 120)
  line L3 (-6.125, 97.2) -> (-6.125, 120)
  line L4 (6.125, 97.2) -> (-6.125, 97.2)
  line L5 (6.125, 97.2) -> (-6.125, 120)
  line L6 (-6.125, 124.745) -> (-6.125, 120)
  line L7 (6.125, 124.745) -> (-6.125, 124.745)
  line L8 (6.125, 120) -> (6.125, 124.745)
  line L9 (-6.125, 92.455) -> (-6.125, 97.2)
  line L10 (6.125, 92.455) -> (-6.125, 92.455)
  line L11 (6.125, 97.2) -> (6.125, 92.455)
  line L12 (6.125, 120) -> (-6.125, 124.745)
  line L13 (6.125, 92.455) -> (-6.125, 97.2)
  circle C1 centre (0, 108.6) radius 2
  circle C2 centre (0, 122.3725) radius 1.5
  circle C3 centre (0, 94.8275) radius 1.5
  circle C4 centre (0, 108.6) radius 3.425
  point P4 (-6.125, 120)
  point P7 (-6.125, 120)
  point P2 (6.125, 97.2)
  point P8 (6.125, 97.2)
  point P6 (0, 108.6)
  point P9 (-6.125, 120)
  point P3 (6.125, 120)
  point P12 (6.125, 120)
  point P5 (-6.125, 97.2)
  point P13 (-6.125, 97.2)
  point P16 (6.125, 97.2)
  point P17 (0, 122.3725)
  point P18 (0, 94.8275)
  coincident P4 P7
  coincident P2 P8
  midpoint P6 L5
  coincident P4 P9
  perpendicular L2 L6
  perpendicular L1 L7
  coincident P3 P12
  perpendicular L7 L8
  coincident P5 P13
  perpendicular L4 L9
  perpendicular L1 L10
  coincident P2 P16
  perpendicular L4 L11
  midpoint L12 P17
  midpoint L13 P18
  concentric C1 C4
  dimension "d956" diameter C1 = 4
  dimension "d1202" distance L2 L7 = 4.745 (= "servo_ears_width")
  dimension "d1203" distance L4 L10 = 4.745 (= "servo_ears_width")
  dimension "d1204" diameter C2 = 3 (= "servo_ears_holes")
  dimension "d1205" diameter C3 = 3 (= "servo_ears_holes")
  dimension "d1208" diameter C4 = 6.85 (= "servo_axle_diameter")
extrude "Extrude2" add sketch "Sketch2" profile of C1 along normal blind 5 (= "servo_axle_length")
extrude "Extrude5" add sketch "Sketch2" profile of C1 C4 along normal blind 2.5 (= "servo_axle_length / 2")
sketch "Sketch3" plane through (0, 0, 33.8) normal (0, 0, 1) x axis (1, 0, 0)
  curve K1 (0, 125.3267) -> (0, 91.8733)
  curve K2 (-3.4771, 108.6) -> (3.4771, 108.6)
  circle C1 centre (0, 108.6) radius 2
  closed curve K3 centre (0, 108.6)
  circle C2 centre (0, 121.6) radius 1
  circle C3 centre (0, 95.6) radius 1
  point P4 (0, 91.8733)
  point P5 (0, 125.3267)
  point P6 (3.4771, 108.6)
  point P7 (-3.4771, 108.6)
  point P8 (0, 121.6)
  point P9 (0, 95.6)
  point P2 (0, 108.6)
  point P3 (0, 108.6)
  concentric C1 K3
  vertical K1
  coincident K3 P4
  coincident K3 P5
  coincident K3 P6
  coincident K3 P7
  coincident K1 P8
  coincident K1 P9
  dimension "d961" diameter C2 = 2
  dimension "d962" diameter C3 = 2
  dimension "d963" distance P2 P8 = 13
  dimension "d964" distance P3 P9 = 13 (= "d963")
extrude "Extrude3" new body sketch "Sketch3" profile of C1 K3 C2 C3 no distance stored
extrude "Extrude4" add sketch "Sketch2" profile of L2 L4 L6 L7 L8 L9 L10 L11 C2 C3 no distance stored
component_from_bodies "Body->Comp1"
component_from_bodies "Body->Comp2"
joint "Assemble1" alignAngle 0 alignOffsetX 0 alignOffsetY 0 alignOffsetZ 0
position "Position13"
position "Position1"
sketch "Sketch3" plane through (0, -5, 88) normal (0, 0, -1) x axis (-1, 0, 0)
  line L1 (-6.125, 87.2) -> (-6.125, 110)
  line L2 (6.125, 87.2) -> (-6.125, 87.2)
  line L3 (6.125, 110) -> (6.125, 87.2)
  line L4 (-6.125, 110) -> (6.125, 110)
  line L5 (-6.125, 114.745) -> (-6.125, 110)
  line L6 (6.125, 114.745) -> (-6.125, 114.745)
  line L7 (6.125, 110) -> (6.125, 114.745)
  line L8 (-6.125, 82.455) -> (6.125, 82.455)
  line L9 (-6.125, 110) -> (6.125, 110)
  line L10 (6.125, 87.2) -> (-6.125, 87.2)
  line L11 (6.325, 87) -> (-6.325, 87)
  line L12 (6.325, 110.2) -> (6.325, 87)
  line L13 (-6.325, 110.2) -> (6.325, 110.2)
  line L14 (-6.325, 87) -> (-6.325, 110.2)
  line L15 (-7.925, 85.4) -> (-7.925, 111.8)
  line L16 (7.925, 85.4) -> (-7.925, 85.4)
  line L17 (7.925, 111.8) -> (7.925, 85.4)
  line L18 (-7.925, 111.8) -> (7.925, 111.8)
  line L19 (14.925, 111.8) -> (7.925, 111.8)
  line L20 (14.925, 85.4) -> (14.925, 111.8)
  line L21 (7.925, 85.4) -> (14.925, 85.4)
  line L22 (-14.925, 85.4) -> (-7.925, 85.4)
  line L23 (-14.925, 111.8) -> (-14.925, 85.4)
  line L24 (-7.925, 111.8) -> (-14.925, 111.8)
  line L25 (2.4027, 121.8) -> (-2.4027, 121.8)
  line L26 (2.4027, 111.8) -> (2.4027, 121.8)
  line L27 (-2.4027, 111.8) -> (2.4027, 111.8)
  line L28 (-2.4027, 121.8) -> (-2.4027, 111.8)
  line L29 (-6.125, 110) -> (6.125, 110)
  line L30 (6.125, 82.455) -> (6.125, 87.2)
  line L31 (-6.125, 87.2) -> (-6.125, 82.455)
  line L32 (6.125, 87.2) -> (-6.125, 87.2)
  circle C1 centre (0, 84.8275) radius 1.5
  circle C2 centre (0, 112.3725) radius 1.5
  circle C3 centre (11.325, 108.2) radius 2
  circle C4 centre (11.325, 89) radius 2
  circle C5 centre (-11.325, 89) radius 2
  circle C6 centre (-11.325, 108.2) radius 2
  point P36 (0, 111.8)
  point P28 (11.325, 108.2)
  point P29 (11.325, 89)
  point P30 (-11.325, 89)
  point P31 (-11.325, 108.2)
  point P32 (-2.4027, 121.8)
  point P35 (-2.4027, 111.8)
  perpendicular L17 L19
  perpendicular L16 L20
  perpendicular L17 L21
  perpendicular L12 L22
  perpendicular L18 L23
  perpendicular L15 L24
  horizontal L25
  vertical L26
  horizontal L27
  vertical L28
  midpoint L27 P36
  midpoint L18 P36
  dimension "d1211" = 0.2 (= "servo_enclosure_margin")
  dimension "d1213" = 1.8 (= "servo_enclosure_margin + servo_enclosure_wall_thickness")
  dimension "d1216" distance L17 L20 = 7 (= "servo_enclosure_ears_width")
  dimension "d1217" distance L15 L23 = 7 (= "d1216")
  dimension "d1248" diameter C3 = 4 (= "servo_enclosure_ears_screws")
  dimension "d1250" distance L19 P28 = 3.6 (= "servo_enclosure_ears_screws / 2 + servo_enclosure_wall_thickness")
  dimension "d1251" distance L20 P28 = 3.6 (= "d1250")
  dimension "d1252" diameter C6 = 4 (= "d1248")
  dimension "d1253" diameter C5 = 4 (= "d1248")
  dimension "d1254" diameter C4 = 4 (= "d1248")
  dimension "d1255" distance L20 P29 = 3.6 (= "d1250")
  dimension "d1256" distance L21 P29 = 3.6 (= "d1250")
  dimension "d1257" distance L22 P30 = 3.6 (= "d1250")
  dimension "d1258" distance L23 P30 = 3.6 (= "d1250")
  dimension "d1259" distance L24 P31 = 3.6 (= "d1250")
  dimension "d1260" distance L23 P31 = 3.6 (= "d1250")
  dimension "d1273" distance P32 P35 = 10
  dimension "d1261" OffsetX = 0
  dimension "d1262" OffsetY = 0
  dimension "d1263" OffsetZ = 0
  dimension "d1264" AngleZ = 0
  dimension "d1298" OffsetX = 0
  dimension "d1299" OffsetY = 0
  dimension "d1300" OffsetZ = 0
  dimension "d1301" AngleZ = 0
  dimension "d1597" OffsetX = 0
  dimension "d1598" OffsetY = 0
  dimension "d1599" OffsetZ = 0
  dimension "d1600" AngleZ = 0
extrude "Extrude1" new body sketch "Sketch3" profile of C1 C2 L5 L7 L14 L13 L12 L11 L17 L16 L18 L15 L27 L30 L31 no distance stored
extrude "Extrude2" add sketch "Sketch3" profile of L17 L15 L19 L20 L21 L22 L23 L24 C3 C4 C5 C6 no distance stored
sketch "Sketch4" plane through (0, 106.8, 0) normal (0, 1, 0) x axis (-1, 0, 0)
  line L1 (14.925, 88) -> (-14.925, 88)
  line L2 (14.925, 89.6) -> (14.925, 88)
  line L3 (7.925, 89.6) -> (14.925, 89.6)
  line L4 (7.925, 104.16) -> (7.925, 89.6)
  line L5 (-7.925, 104.16) -> (7.925, 104.16)
  line L6 (-7.925, 89.6) -> (-7.925, 104.16)
  line L7 (-14.925, 89.6) -> (-7.925, 89.6)
  line L8 (-14.925, 88) -> (-14.925, 89.6)
  line L9 (6, 97.76) -> (7.925, 97.76)
  line L10 (6, 104.16) -> (6, 97.76)
  line L11 (-6, 104.16) -> (-6, 97.76)
  line L12 (-7.925, 97.76) -> (-6, 97.76)
  line L13 (-6, 97.76) -> (6, 97.76)
  line L14 (-6, 104.16) -> (6, 97.76)
  line L15 (2.2, 100.085) -> (-2.2, 100.085)
  line L16 (2.2, 101.835) -> (2.2, 100.085)
  line L17 (-2.2, 101.835) -> (2.2, 101.835)
  line L18 (-2.2, 100.085) -> (-2.2, 101.835)
  line L19 (2.2, 101.835) -> (-2.2, 100.085)
  line L20 (-2.2, 101.835) -> (2.2, 100.085)
  line L21 (-2.25, 88) -> (2.25, 88)
  line L22 (-2.25, 94.5) -> (-2.25, 88)
  line L23 (2.25, 94.5) -> (-2.25, 94.5)
  line L24 (2.25, 88) -> (2.25, 94.5)
  point P10 (7.925, 97.76)
  point P11 (6, 97.76)
  point P12 (6, 104.16)
  point P13 (-6, 97.76)
  point P14 (-6, 104.16)
  point P15 (-7.925, 97.76)
  point P20 (0, 100.96)
  point P21 (2.25, 88)
  point P17 (2.2, 100.085)
  point P18 (2.2, 101.835)
  point P19 (-2.2, 101.835)
  point P24 (2.25, 94.5)
  point P23 (-2.25, 94.5)
  coincident L4 P10
  perpendicular L4 L9
  coincident L9 P11
  coincident L5 P12
  perpendicular L5 L10
  coincident L9 P13
  coincident L5 P14
  perpendicular L5 L11
  coincident L6 P15
  perpendicular L6 L12
  equal L9 L12
  perpendicular L15 L16
  parallel L15 L17
  parallel L16 L18
  horizontal L15
  coincident L19 P20
  coincident L20 P20
  midpoint L14 P20
  horizontal L21
  vertical L22
  horizontal L23
  vertical L24
  coincident L1 P21
  midpoint L1 L21
  dimension "d1223" distance L5 L9 = 6.4 (= "servo_enclosure_wall_thickness * 4")
  dimension "d1227" distance L10 L11 = 12 (= "servo_ears_holes * 4")
  dimension "d1235" distance P17 P18 = 1.75
  dimension "d1236" distance P18 P19 = 4.4
  dimension "d1332" distance P21 P24 = 6.5 (= "servo_enclosure_cable_hole_height")
  dimension "d1333" distance P23 P24 = 4.5 (= "servo_enclosure_cable_hole_width")
extrude "Extrude3" add sketch "Sketch4" profile of L5 L10 L11 L13 no distance stored
extrude "Extrude7" sketch "Sketch4" profile of L5 L10 L11 L13 L15 L16 L17 L18 no distance stored
chamfer "Chamfer2" distance 2.945 (= "servo_ears_width - servo_enclosure_wall_thickness - servo_enclosure_margin")
sketch "Sketch6" plane through (0, -5, 104.36) normal (0, 0, -1) x axis (-1, 0, 0)
  line L1 (-6.125, 114.745) -> (6.125, 114.745)
  line L2 (-6.125, 110) -> (-6.125, 114.745)
  line L3 (6.125, 110) -> (-6.125, 110)
  line L4 (6.125, 114.745) -> (6.125, 110)
  line L5 (6.125, 87.2) -> (6.125, 82.455)
  line L6 (-6.125, 87.2) -> (6.125, 87.2)
  line L7 (-6.125, 82.455) -> (-6.125, 87.2)
  line L8 (6.125, 82.455) -> (-6.125, 82.455)
  circle C1 centre (0, 112.3725) radius 1.5
  circle C2 centre (0, 84.8275) radius 1.5
joint_origin "JointOrigin2" OffsetX 0 OffsetY 0 OffsetZ 0 AngleZ 0
joint_origin "JointOrigin3" OffsetX 0 OffsetY 0 OffsetZ 0 AngleZ 0
extrude "Extrude8" cut sketch "Sketch6" profile of C1 C2 along normal blind 10
extrude "Extrude9" cut sketch "Sketch4" profile of L15 L16 L17 L18 no distance stored
joint "Assemble2" alignAngle 0 alignOffsetX 0 alignOffsetY 0 alignOffsetZ 0
extrude "Extrude1" cut sketch "Sketch4" profile of L1 L21 L22 L23 L24 no distance stored
sketch "Sketch7" plane through (0, 0, 94.5) normal (0, 0, -1) x axis (-1, 0, 0)
  line L1 (2.25, 105.2) -> (-2.25, 105.2)
  line L2 (2.25, 106.8) -> (2.25, 105.2)
  line L3 (1.3865, 106.8) -> (2.25, 106.8)
  line L4 (-2.25, 106.8) -> (-1.3865, 106.8)
  line L5 (-2.25, 105.2) -> (-2.25, 106.8)
  line L6 (-2.25, 105.2) -> (-2.25, 106.8)
  line L7 (2.25, 106.8) -> (2.25, 105.2)
  line L8 (1.3865, 106.8) -> (-1.3865, 106.8)
  line L9 (1.3865, 105.2) -> (1.3865, 106.8)
  line L10 (-1.3865, 105.2) -> (1.3865, 105.2)
  line L11 (-1.3865, 106.8) -> (-1.3865, 105.2)
  line L12 (1.3408, 80.5) -> (-1.3408, 80.5)
  line L13 (1.3408, 81.7) -> (1.3408, 80.5)
  line L14 (-1.3408, 81.7) -> (1.3408, 81.7)
  line L15 (-1.3408, 80.5) -> (-1.3408, 81.7)
  line L16 (-2.25, 106.8) -> (-1.3865, 106.8)
  line L17 (2.25, 105.2) -> (-2.25, 105.2)
  line L18 (1.3865, 106.8) -> (2.25, 106.8)
  arc A1 centre (0, 107.3725) radius 1.5 clockwise from (1.3865, 106.8) to (-1.3865, 106.8)
  arc A2 centre (0, 107.3725) radius 1.5 clockwise from (1.3865, 106.8) to (-1.3865, 106.8)
  point P5 (1.3865, 106.8)
  point P14 (1.3865, 106.8)
  point P6 (-1.3865, 106.8)
  point P13 (-1.3865, 106.8)
  perpendicular L8 L9
  parallel L8 L10
  parallel L9 L11
  coincident P5 P14
  parallel L3 L8
  coincident P6 P13
  perpendicular L12 L13
  parallel L12 L14
  parallel L13 L15
  perpendicular L11 L12
  collinear L10 L17
extrude "Extrude11" cut sketch "Sketch7" profile of L1 L2 L3 A1 L4 L5 L6 L7 L9 L10 L11 A2 L16 L17 L18 against normal blind 16
fillet "Fillet2" radius 1.6 (= "servo_enclosure_wall_thickness")
ground "Ground1"
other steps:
base_feature "Base Feature1" OffsetX 0 OffsetY 0 OffsetZ 0 AngleZ 0 OffsetX 0 OffsetY 0 OffsetZ 0 AngleZ 0 OffsetX 0 OffsetY 0 OffsetZ 0 AngleZ 0 OffsetX 0 OffsetY 0 OffsetZ 0 AngleZ 0 OffsetX 0 OffsetY 0 OffsetZ 0 AngleZ 0 OffsetX 0 OffsetY 0 OffsetZ 0 AngleZ 0 OffsetX 0 OffsetY 0 OffsetZ 0 AngleZ 0
base_feature "Base Feature1" OffsetX 0 OffsetY 0 OffsetZ 0 AngleZ 0 OffsetX 0 OffsetY 0 OffsetZ 0 AngleZ 0 OffsetX 0 OffsetY 0 OffsetZ 0 AngleZ 0 OffsetX 0 OffsetY 0 OffsetZ 0 AngleZ 0 OffsetX 0 OffsetY 0 OffsetZ 0 AngleZ 0 OffsetX 0 OffsetY 0 OffsetZ 0 AngleZ 0
extrude "Extrude10" cut sketch "Sketch4" profile of L1 L21 L22 L23 L24 no distance stored
create_component "CreateComponent1"
remove_body "RemoveBody1"
create_component "CreateComponent2"
remove_body "RemoveBody2"
joint_origin "JointOrigin3" OffsetX 0 OffsetY 0 OffsetZ 0 AngleZ 0
joint_origin "JointOrigin4" OffsetX 0 OffsetY 0 OffsetZ 0 AngleZ 0
create_component "CreateComponent3"
joint_origin "JointOrigin5" OffsetX 0 OffsetY 0 OffsetZ 0 AngleZ 0
joint_origin "JointOrigin7" OffsetX 0 OffsetY 0 OffsetZ 0 AngleZ 0

design "Arcade Button_30mm"
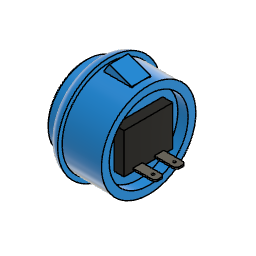
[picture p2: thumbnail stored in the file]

design "EIP Cupholder PCB"
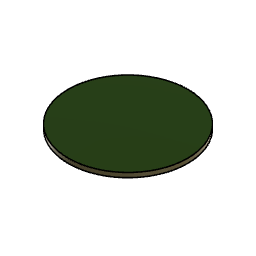
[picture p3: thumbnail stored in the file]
derived_context "DerivedContext1"
sketch "Outline" plane through (0, 0, 0) normal (0, 0, 1) x axis (1, 0, 0)
step sketch "pcb-sketch"
canvas "Canvas1" bodies "Board"
canvas "Canvas2" bodies "Board"
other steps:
pcbextrude "PCBExtrude"
pcbextrude "PCBExtrude1"
derived_base_feature "pcb-sketch"
derived_base_feature "Base Feature"
box_primitive "BoxPrimitive1" DistanceX 8 DistanceY 3.81 DistanceZ 0.1 OffsetDistanceX 0 OffsetDistanceY 0
base_feature "Base Feature"
box_primitive "BoxPrimitive1" DistanceX 20 DistanceY 17.95 DistanceZ 1 OffsetDistanceX 0 OffsetDistanceY 0
pcbextrude "PCBExtrude1"
pcbextrude "PCBExtrude1"
extrude "Extrude1" sketch "pcb-sketch" blind 1.5 bodies "Board"
pcbextrude "PCBExtrude1"
pcbextrude "PCBExtrude"
create_component "CreateComponent1"
create_component "CreateComponent2"
create_component "CreateComponent3"
create_component "CreateComponent4"
create_component "CreateComponent5"
create_component "CreateComponent6"
create_component "CreateComponent3"
as_built_joint "As-built1"
create_component "CreateComponent5"
create_component "CreateComponent6"
step "CreateComponent"
named bodies: "Board"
